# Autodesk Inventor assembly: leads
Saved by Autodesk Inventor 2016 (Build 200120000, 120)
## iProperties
Created: 2018-05
Part Number: leads
Document SubType Name: Assembly
Designer: Administrator
Title: leads
Author: Administrator
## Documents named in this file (3)
- c:\worker\convert-fusion-mar-2018\tmp\job-1\16\output\files\8c58ff39-88bb-4352-afd9-60265520bae5\leads_1.iam
- c:\worker\convert-fusion-mar-2018\tmp\job-1\16\output\files\8c58ff39-88bb-4352-afd9-60265520bae5\top_lead.ipt
- c:\worker\convert-fusion-mar-2018\tmp\job-1\16\output\files\8c58ff39-88bb-4352-afd9-60265520bae5\bottom_lead.ipt
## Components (8 placed, 2 different names)
1. top_lead:1
2. top_lead:5
3. top_lead:6
4. top_lead:7
5. bottom_lead:1
6. bottom_lead:8
7. bottom_lead:9
8. bottom_lead:10
